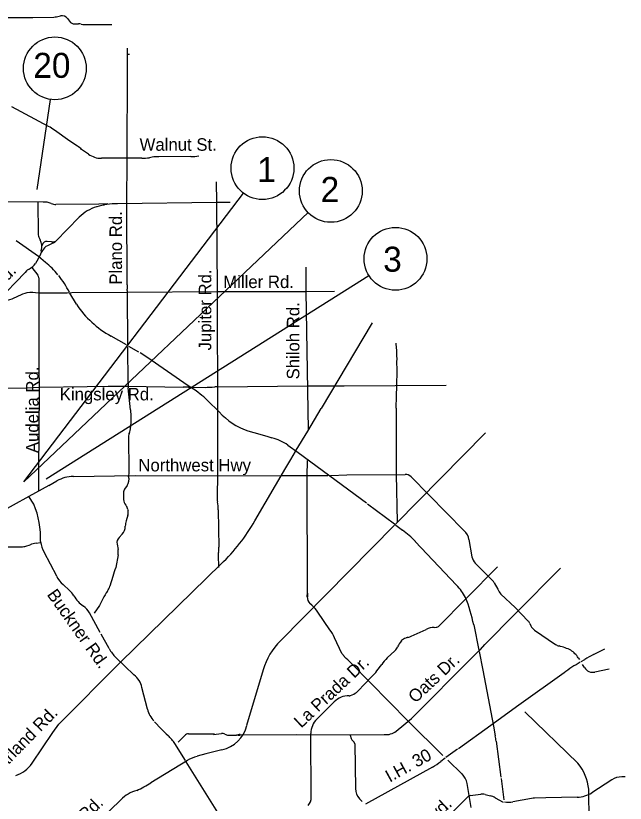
# Model space of a CAD drawing. Extents: x 105094 to 105814, y -291615 to -291123.
# Drawn here: x 105486.2 to 105545.1, y -291448 to -291371.9 of the extents above; entities that cross this region are included whole.
import ezdxf

# ---------------------------------------------------------------- set-up
doc = ezdxf.new("R2010")
doc.units = 0
doc.layers.add('G_BORDER', color=7, linetype='Continuous')
doc.layers.add('G_MAP', color=7, linetype='Continuous')

msp = doc.modelspace()

# ---------------------------------------------------------------- linework, layer by layer
at = {"layer": 'G_BORDER'}
for p, q in [((105488.251, -291388.669), (105489.525, -291379.944)), ((105486.954, -291416.932), (105508.197, -291389.007)), ((105486.954, -291416.932), (105514.44, -291390.884)), ((105489.114, -291416.641), (105520.33, -291396.975))]:
    msp.add_line(p, q, dxfattribs=at)
for centre in [(105489.964, -291376.941), (105510.034, -291386.591), (105516.643, -291388.796), (105522.898, -291395.357)]:
    msp.add_circle(centre, 3.035, dxfattribs=at)
at = {"layer": 'G_MAP'}
for p, q in [((105484.337, -291372.036), (105487.826, -291372.012)), ((105487.826, -291372.012), (105489.856, -291371.98)), ((105490.39, -291371.907), (105490.492, -291371.879)), ((105491.199, -291372.134), (105491.383, -291372.394)), ((105491.862, -291372.639), (105492.254, -291372.634)), ((105497.017, -291375.567), (105497.172, -291375.567)), ((105489.337, -291382.576), (105485.809, -291380.678)), ((105493.212, -291385.246), (105492.55, -291384.788)), ((105498.365, -291385.64), (105494.462, -291385.637)), ((105499.384, -291385.54), (105499.104, -291385.584)), ((105503.121, -291385.475), (105500.02, -291385.501)), ((105488.846, -291389.877), (105484.693, -291389.835)), ((105488.329, -291389.871), (105488.349, -291392.921)), ((105489.61, -291390.021), (105489.33, -291389.916)), ((105494.714, -291390.197), (105494.685, -291390.087)), ((105496.939, -291397.867), (105496.917, -291390.058)), ((105492.324, -291391.338), (105490.051, -291393.653)), ((105491.068, -291392.687), (105491.003, -291392.616)), ((105488.461, -291393.387), (105488.53, -291393.514)), ((105488.365, -291395.145), (105486.217, -291393.63)), ((105488.73, -291394.029), (105488.707, -291394.118)), ((105489.651, -291393.72), (105489.227, -291393.68)), ((105489.818, -291393.817), (105489.247, -291394.094)), ((105488.494, -291395.064), (105488.1, -291395.807)), ((105488.639, -291394.744), (105488.494, -291395.064)), ((105488.634, -291394.58), (105488.639, -291394.744)), ((105488.771, -291394.57), (105488.639, -291394.744)), ((105489.065, -291395.705), (105488.365, -291395.145)), ((105487.224, -291396.514), (105487.099, -291396.685)), ((105487.732, -291396.197), (105488.316, -291396.944)), ((105487.099, -291396.685), (105483.821, -291400.044)), ((105488.378, -291398.636), (105491.136, -291398.636)), ((105491.136, -291398.636), (105491.604, -291398.632)), ((105492.059, -291399.759), (105491.423, -291398.671)), ((105497.03, -291403.68), (105496.998, -291398.675)), ((105520.648, -291401.566), (105515.713, -291409.841)), ((105496.875, -291403.69), (105495.392, -291402.824)), ((105497.046, -291407.368), (105497.03, -291403.87)), ((105498.092, -291404.39), (105497.127, -291403.832)), ((105497.033, -291407.681), (105502.368, -291407.759)), ((105497.279, -291409.958), (105497.062, -291407.839)), ((105502.895, -291407.765), (105502.368, -291407.759)), ((105503.618, -291408.133), (105502.837, -291407.633)), ((105502.895, -291407.765), (105504.535, -291407.788)), ((105505.165, -291407.762), (105505.437, -291407.749)), ((105517.928, -291407.629), (105527.797, -291407.592)), ((105504.72, -291409.047), (105504.364, -291408.721)), ((105505.847, -291410.166), (105504.72, -291409.047)), ((105488.411, -291417.809), (105488.43, -291410.04)), ((105522.973, -291409.789), (105522.963, -291414.875)), ((105505.685, -291410.731), (105505.695, -291416.024)), ((105508.61, -291411.982), (105509.215, -291412.169)), ((105509.215, -291412.169), (105510.452, -291412.524)), ((105510.452, -291412.524), (105510.95, -291412.656)), ((105531.608, -291412.173), (105522.918, -291420.998)), ((105512.497, -291413.367), (105513.494, -291414.1)), ((105513.494, -291414.1), (105520.089, -291418.97)), ((105509.303, -291420.688), (105512.296, -291415.585)), ((105491.755, -291416.399), (105497.718, -291416.321)), ((105505.695, -291416.024), (105505.658, -291418.576)), ((105511.986, -291416.309), (105516.372, -291416.302)), ((105489.37, -291417.286), (105490.147, -291416.84)), ((105524.4, -291416.438), (105529.533, -291421.667)), ((105489.37, -291417.286), (105487.451, -291418.332)), ((105496.943, -291417.274), (105496.711, -291417.63)), ((105487.451, -291418.332), (105481.125, -291421.859)), ((105487.936, -291419.094), (105487.451, -291418.332)), ((105496.607, -291417.979), (105496.607, -291418.631)), ((105496.815, -291419.191), (105496.853, -291419.235)), ((105520.189, -291419.038), (105522.792, -291420.995)), ((105497.007, -291420.157), (105496.849, -291420.704)), ((105497.023, -291419.6), (105497.036, -291419.679)), ((105505.768, -291419.618), (105505.814, -291423.231)), ((105522.805, -291421.111), (105511.765, -291432.298)), ((105522.792, -291420.995), (105522.944, -291421.114)), ((105522.944, -291421.114), (105523.58, -291421.602)), ((105496.455, -291422.001), (105496.175, -291422.294)), ((105484.35, -291423.199), (105486.735, -291423.209)), ((105487.155, -291423.143), (105487.564, -291423.009)), ((105488.143, -291422.847), (105488.581, -291422.793)), ((105495.979, -291422.948), (105496.074, -291423.466)), ((105524.817, -291422.687), (105528.809, -291426.913)), ((105530.004, -291422.516), (105530.293, -291424.168)), ((105490.136, -291426.054), (105488.923, -291423.74)), ((105496.074, -291423.981), (105495.842, -291425.215)), ((105505.759, -291423.995), (105505.789, -291425.215)), ((105530.608, -291424.781), (105532.087, -291426.285)), ((105529.778, -291428.181), (105532.775, -291425.129)), ((105538.855, -291425.264), (105534.496, -291429.654)), ((105495.577, -291426.07), (105495.284, -291427.021)), ((105491.366, -291427.418), (105490.755, -291426.858)), ((105532.439, -291426.692), (105532.782, -291427.306)), ((105533.079, -291427.79), (105534.477, -291429.082)), ((105527.107, -291430.838), (105529.675, -291428.274)), ((105514.796, -291428.845), (105514.63, -291428.685)), ((105534.477, -291429.082), (105535.74, -291430.388)), ((105494.337, -291431.489), (105493.309, -291429.598)), ((105516.54, -291431.225), (105515.4, -291429.53)), ((105531.551, -291432.66), (105534.496, -291429.653)), ((105530.46, -291430.761), (105530.954, -291433.199)), ((105535.891, -291430.608), (105535.999, -291430.844)), ((105495.209, -291433.051), (105494.431, -291431.641)), ((105524.43, -291431.849), (105525.867, -291431.194)), ((105526.639, -291431), (105526.817, -291430.98)), ((105536.349, -291431.258), (105538.374, -291432.644)), ((105523.463, -291432.313), (105523.493, -291432.275)), ((105523.887, -291432.056), (105523.933, -291432.017)), ((105530.834, -291433.396), (105531.128, -291433.125)), ((105531.128, -291433.125), (105531.551, -291432.66)), ((105542.041, -291433.625), (105543.153, -291433.084)), ((105497.609, -291435.588), (105495.866, -291433.908)), ((105522.105, -291433.958), (105522.841, -291433.254)), ((105530.418, -291433.8), (105530.712, -291433.519)), ((105530.712, -291433.519), (105530.831, -291433.396)), ((105530.976, -291433.341), (105531.338, -291435.124)), ((105521.087, -291435.211), (105521.565, -291434.581)), ((105540.57, -291433.94), (105540.684, -291434.116)), ((105540.862, -291434.291), (105541.195, -291434.1)), ((105541.169, -291434.888), (105540.978, -291434.581)), ((105510.104, -291435.108), (105508.508, -291440.474)), ((105531.338, -291435.124), (105532.365, -291440.562)), ((105539.195, -291435.39), (105534.829, -291438.525)), ((105543.547, -291435.047), (105542.189, -291435.327)), ((105519.25, -291437.171), (105520.626, -291435.747)), ((105498.921, -291438.919), (105498.387, -291436.815)), ((105518.555, -291437.593), (105518.725, -291437.525)), ((105515.287, -291439.871), (105516.977, -291438.19)), ((105534.829, -291438.525), (105532.133, -291440.485)), ((105540.533, -291444.14), (105535.414, -291439.154)), ((105500.248, -291440.808), (105499.608, -291440.122)), ((105532.133, -291440.485), (105528.977, -291442.749)), ((105532.365, -291440.562), (105532.543, -291441.48)), ((105501.881, -291442.098), (105502.521, -291441.445)), ((105502.877, -291441.295), (105505.398, -291441.285)), ((105505.308, -291441.352), (105506.069, -291441.26)), ((105506.738, -291441.421), (105507.523, -291441.411)), ((105514.754, -291447.44), (105514.708, -291441.259)), ((105518.51, -291441.408), (105518.602, -291441.737)), ((105502.598, -291443.881), (105501.564, -291442.241)), ((105518.681, -291441.876), (105518.887, -291442.093)), ((105518.958, -291442.266), (105519.02, -291446.583)), ((105532.624, -291442.012), (105533.073, -291445.487)), ((105528.897, -291442.784), (105527.773, -291443.595)), ((105527.698, -291443.643), (105527.292, -291443.953)), ((105502.771, -291443.868), (105499.243, -291446.039)), ((105505.719, -291448.885), (105502.663, -291443.988)), ((105526.465, -291444.508), (105519.999, -291448.096)), ((105529.341, -291445.177), (105527.97, -291443.85)), ((105530.218, -291448.416), (105529.816, -291446.081)), ((105533.108, -291445.626), (105533.376, -291447.664)), ((105543.823, -291445.736), (105541.891, -291446.984)), ((105541.705, -291453.857), (105541.589, -291446.659)), ((105519.429, -291447.585), (105519.673, -291447.838)), ((105526.657, -291450.614), (105529.889, -291447.382)), ((105530.13, -291447.262), (105531.15, -291447.125)), ((105531.555, -291447.146), (105532.075, -291447.273)), ((105532.533, -291447.483), (105533.312, -291447.903)), ((105536.059, -291447.543), (105534.24, -291447.871)), ((105537.423, -291447.473), (105536.356, -291447.515)), ((105540.474, -291447.416), (105537.423, -291447.473))]:
    msp.add_line(p, q, dxfattribs=at)
for points in [[(105492.806, -291372.703), (105494.899, -291372.703), (105495.467, -291372.702)], [(105496.917, -291390.058), (105496.968, -291385.653), (105496.978, -291376.953), (105496.996, -291375.006)], [(105492.153, -291384.481), (105491.404, -291383.98), (105489.915, -291382.928)], [(105505.574, -291387.932), (105505.594, -291389.877)], [(105495.069, -291390.055), (105494.22, -291390.084), (105490.067, -291390.103)], [(105506.898, -291389.926), (105505.601, -291389.925), (105496.021, -291390.032)], [(105505.594, -291389.877), (105505.659, -291398.538), (105505.685, -291410.731)], [(105514.479, -291411.902), (105514.269, -291398.509), (105514.256, -291396.178)], [(105488.4, -291397.188), (105488.407, -291403.645), (105488.43, -291410.039)], [(105491.604, -291398.632), (105496.997, -291398.581), (105505.662, -291398.535), (105514.263, -291398.512), (105517.008, -291398.498)], [(105523.031, -291404.661), (105523.015, -291404.257), (105522.963, -291403.583), (105522.962, -291403.516)], [(105502.837, -291407.633), (105498.858, -291404.868), (105498.196, -291404.449)], [(105522.973, -291409.786), (105522.983, -291408.64), (105523.021, -291407.645), (105523.063, -291406.156), (105523.044, -291405.262)], [(105483.13, -291407.888), (105487.173, -291407.827), (105488.485, -291407.785), (105493.093, -291407.704), (105495.115, -291407.662), (105497.033, -291407.681)], [(105505.695, -291407.736), (105514.389, -291407.632), (105517.928, -291407.629)], [(105497.279, -291409.959), (105497.301, -291410.573), (105497.301, -291411.073), (105497.28, -291411.641)], [(105513.304, -291413.858), (105514.428, -291412.017), (105515.713, -291409.844)], [(105497.098, -291412.48), (105497.104, -291416.024), (105497.092, -291416.399)], [(105512.296, -291415.585), (105512.765, -291414.752), (105513.223, -291413.993)], [(105514.383, -291427.699), (105514.366, -291416.373), (105514.392, -291414.878)], [(105522.963, -291414.875), (105522.964, -291416.202), (105523.057, -291420.795)], [(105497.718, -291416.321), (105505.679, -291416.341), (105511.964, -291416.305)], [(105516.614, -291416.322), (105518.184, -291416.264), (105523.826, -291416.201)], [(105487.764, -291444.137), (105489.758, -291441.171), (105490.355, -291440.367), (105496.323, -291434.351), (105506.044, -291424.86)], [(105494.596, -291428.246), (105494.263, -291428.883), (105493.746, -291429.623)], [(105517.977, -291433.848), (105517.977, -291433.825), (105517.703, -291433.509), (105516.999, -291432.004)], [(105522.967, -291441.027), (105524.437, -291439.816), (105530.418, -291433.8)], [(105527.485, -291443.385), (105524.133, -291440.055), (105518.61, -291434.465)], [(105507.872, -291441.385), (105513.33, -291441.369), (105514.648, -291441.388), (105521.811, -291441.347)], [(105506.119, -291442.825), (105504.572, -291443.238), (105503.707, -291443.468)], [(105545.115, -291445.454), (105544.774, -291445.455)], [(105496.336, -291447.662), (105486.88, -291456.847), (105486.383, -291457.341)]]:
    msp.add_lwpolyline(points, dxfattribs=at)
for centre, radius, start, end in [((105489.841, -291369.884), 2.096, 270.39765, 285.19367), ((105490.664, -291372.511), 0.655, 35.19875, 105.20005), ((105491.855, -291372.061), 0.578, 215.21916, 270.70004), ((105492.261, -291373.673), 1.039, 75.57891, 90.41542), ((105492.806, -291371.555), 1.148, 255.55069, 270.00019), ((105488.574, -291384.479), 2.05, 49.16169, 68.16293), ((105491.241, -291386.073), 1.835, 44.4606, 60.18033), ((105494.463, -291383.439), 2.198, 235.30065, 269.95014), ((105498.369, -291380.854), 4.787, 269.9494, 278.83232), ((105499.84, -291387.786), 2.291, 85.4926, 101.48183), ((105503.085, -291381.737), 3.738, 270.54515, 282.3706), ((105488.991, -291391.107), 1.239, 74.11481, 96.74104), ((105490.061, -291388.822), 1.281, 249.36441, 270.27723), ((105495.074, -291394.038), 3.854, 106.12562, 135.53222), ((105496.103, -291397.423), 7.392, 90.63366, 106.49787), ((105489.296, -291392.939), 0.948, 178.9585, 208.25312), ((105487.317, -291394.17), 1.379, 342.74484, 28.41373), ((105489.183, -291394.146), 0.468, 84.60188, 165.52388), ((105489.695, -291395.019), 1.028, 115.85344, 154.059), ((105489.771, -291393.216), 0.518, 256.6181, 302.61243), ((105489.616, -291393.286), 0.569, 290.79874, 319.824), ((105486.685, -291394.814), 1.728, 296.97109, 324.95585), ((105484.252, -291401.629), 7.633, 38.11772, 50.91227), ((105488.089, -291397.574), 1.368, 116.93223, 129.194), ((105488.003, -291397.189), 0.398, 0.07759, 38.02354), ((105481.04, -291404.15), 11.734, 28.39142, 37.63494), ((105507.385, -291398.001), 10.447, 179.26481, 181.60309), ((105495.354, -291398.718), 1.644, 1.46949, 14.95875), ((105499.84, -291394.643), 9.312, 213.33038, 241.47188), ((105517.607, -291405.079), 5.44, 358.06969, 4.40048), ((105499.555, -291407.518), 2.513, 176.577, 187.34946), ((105504.538, -291400.178), 7.61, 269.97727, 274.72399), ((105505.613, -291408.687), 0.954, 85.07207, 100.65228), ((105493.547, -291421.684), 16.884, 50.15717, 53.38065), ((105510.718, -291405.764), 6.566, 222.09964, 251.27026), ((105495.57, -291411.579), 1.712, 337.11174, 357.91098), ((105497.688, -291412.48), 0.59, 156.51704, 180.08939), ((105509.108, -291418.705), 6.323, 57.59475, 73.06745), ((105491.801, -291419.721), 3.322, 90.80312, 119.8625), ((105496.162, -291416.691), 0.974, 323.25962, 17.47371), ((105523.835, -291416.993), 0.793, 44.46194, 90.65606), ((105497.246, -291417.979), 0.639, 146.91283, 180.00003), ((105497.465, -291418.631), 0.858, 179.99785, 220.73534), ((105506.725, -291418.582), 1.067, 179.6825, 195.06943), ((105480.346, -291422.271), 8.228, 356.95636, 22.71465), ((105496.292, -291419.718), 0.74, 9.20961, 40.75888), ((105501.03, -291419.688), 4.738, 0.84507, 10.06711), ((105495.967, -291419.855), 1.083, 343.80523, 9.31763), ((105498.655, -291421.227), 1.881, 163.84518, 179.44566), ((105493.37, -291411.603), 18.341, 313.71172, 330.30768), ((105495.627, -291421.207), 1.148, 316.21885, 359.90301), ((105519.31, -291427.718), 7.46, 42.40817, 55.0725), ((105528.764, -291422.649), 1.248, 6.12479, 51.94908), ((105496.718, -291422.813), 0.751, 136.24156, 190.39225), ((105486.74, -291421.879), 1.33, 269.77251, 288.17114), ((105488.656, -291425.802), 2.999, 99.86042, 111.34683), ((105492.727, -291421.83), 4.256, 191.91108, 206.66429), ((105501.292, -291423.291), 4.522, 354.26759, 0.75953), ((105494.696, -291423.721), 1.402, 349.32009, 10.48952), ((105506.617, -291423.977), 0.858, 164.10347, 181.21373), ((105531.434, -291423.969), 1.158, 189.90824, 224.51192), ((105503.9, -291428.177), 8.585, 159.81449, 165.79566), ((105492.754, -291424.679), 2.957, 207.69819, 227.46392), ((105531.441, -291427.2), 1.12, 26.96282, 54.76235), ((105493.706, -291426.538), 1.651, 325.08193, 342.99069), ((105524.665, -291430.828), 5.701, 28.44562, 43.37026), ((105489.819, -291429.106), 2.289, 30.44854, 47.47928), ((105500.817, -291431.503), 7.021, 145.07819, 152.371), ((105513.605, -291427.678), 0.778, 345.02891, 358.46815), ((105515.161, -291427.72), 0.778, 178.46807, 191.90731), ((105536.61, -291425.291), 4.327, 207.75798, 215.28898), ((105494.51, -291426.34), 3.156, 210.5845, 235.33535), ((105515.109, -291428.08), 0.778, 165.02871, 178.46796), ((105515.212, -291428.081), 0.839, 178.61951, 226.07268), ((105513.638, -291428.041), 0.778, 358.46815, 11.90739), ((105516.674, -291433.39), 14.034, 10.79874, 22.08957), ((105491.624, -291430.514), 1.918, 28.51258, 55.34422), ((105512.758, -291431.251), 3.153, 33.09172, 49.73924), ((105526.874, -291430.729), 0.258, 257.2058, 334.89597), ((105535.167, -291430.942), 0.797, 24.75363, 43.99801), ((105536.926, -291430.416), 1.021, 204.77618, 235.6006), ((105514.602, -291432.891), 2.555, 20.32723, 40.68868), ((105526.607, -291432.509), 1.509, 88.80403, 119.37389), ((105516.555, -291437.025), 6.729, 135.3756, 163.44959), ((105525.709, -291434.107), 2.874, 141.37346, 154.82071), ((105523.95, -291432.632), 0.579, 96.22067, 142.04225), ((105524.164, -291432.477), 0.515, 96.28781, 116.66667), ((105524.025, -291431.232), 0.738, 276.37152, 303.25306), ((105498.377, -291431.303), 3.618, 208.89973, 226.05435), ((105521.979, -291432.351), 1.248, 313.66684, 334.71895), ((105538.96, -291431.79), 1.036, 235.54143, 256.58261), ((105537.515, -291437.858), 5.202, 63.19227, 76.60712), ((105506.904, -291445.845), 16.326, 44.18911, 47.29127), ((105538.452, -291435.305), 2.52, 32.80053, 56.01509), ((105546.271, -291442.156), 9.522, 116.37593, 122.21653), ((105524.304, -291436.406), 3.291, 131.9352, 146.32347), ((105553.168, -291454.858), 23.964, 121.20477, 125.66668), ((105518.128, -291433.128), 3.619, 313.64483, 324.86542), ((105541.993, -291434.376), 0.97, 211.85203, 281.6258), ((105496.24, -291437.316), 2.205, 13.14567, 51.62308), ((105518.367, -291439.589), 1.972, 88.69163, 134.81345), ((105518.426, -291437.277), 0.342, 267.50914, 292.10733), ((105518.157, -291436.116), 1.519, 291.95186, 315.99579), ((105501.431, -291438.282), 2.59, 194.24083, 223.08986), ((105516.67, -291441.262), 1.962, 134.8232, 179.89797), ((105505.528, -291439.835), 3.048, 281.16497, 347.89455), ((105508.297, -291433.299), 11.008, 223.01136, 227.8573), ((105498.353, -291444.265), 3.795, 32.22504, 47.63082), ((105502.879, -291441.796), 0.501, 90.21921, 135.60849), ((105506.134, -291441.8), 0.543, 59.22349, 96.87847), ((105506.731, -291440.798), 0.623, 239.22904, 270.65371), ((105507.47, -291440.698), 0.715, 274.27321, 288.29996), ((105507.577, -291442.124), 0.715, 80.24654, 94.27329), ((105507.919, -291442.055), 0.715, 94.27328, 108.30003), ((105507.819, -291440.714), 0.715, 260.24646, 274.27321), ((105522.024, -291439.867), 1.495, 261.80149, 309.10963), ((105529.651, -291442.19), 2.978, 3.42655, 13.80865), ((105518.921, -291441.648), 0.331, 195.54549, 223.46667), ((105518.699, -291442.271), 0.258, 0.98226, 43.51745), ((105504.697, -291447.188), 3.849, 104.9058, 120.11274), ((105485.315, -291442.491), 2.951, 287.03231, 326.08708), ((105524.064, -291440.042), 5.071, 298.25743, 309.52995), ((105537.061, -291447.077), 4.547, 5.26931, 40.22336), ((105528.204, -291446.351), 1.635, 9.53388, 45.93204), ((105493.322, -291436.507), 11.222, 294.00049, 301.84641), ((105544.778, -291447.216), 1.761, 90.14363, 122.84297), ((105498.937, -291450.342), 3.735, 106.33736, 134.14216), ((105520.48, -291446.572), 1.459, 180.41823, 223.96618), ((105513.677, -291447.465), 1.078, 316.09537, 1.2822), ((105530.187, -291447.68), 0.421, 97.68019, 134.97644), ((105531.296, -291448.206), 1.091, 76.25248, 97.70733), ((105531.575, -291448.971), 1.77, 57.21534, 73.59463), ((105536.384, -291449.35), 1.835, 90.86911, 100.1992), ((105540.423, -291444.71), 2.706, 271.08575, 302.84675), ((105533.845, -291445.669), 2.238, 259.77082, 280.18014)]:
    msp.add_arc(centre, radius, start, end, dxfattribs=at)
msp.add_spline([(105463.027, -291396.395), (105466.797, -291396.395), (105468.945, -291397.601), (105472.732, -291398.475), (105476.336, -291397.455), (105480.413, -291397.455), (105482.925, -291398.475), (105484.746, -291399.423), (105486.457, -291398.949), (105487.284, -291398.616), (105488.378, -291398.636)], degree=3, dxfattribs=at)

# ---------------------------------------------------------------- texts
at = {"layer": 'G_BORDER'}
for s, p in [('20', (105487.876, -291377.86)), ('1', (105509.531, -291387.944)), ('2', (105515.661, -291389.857)), ('3', (105521.708, -291396.606))]:
    msp.add_text(s, height=2.416, dxfattribs=at).set_placement(p)
at = {"layer": 'G_MAP'}
for s, height, p in [('Walnut St.', 1.2111, (105498.153, -291384.912)), ('Miller Rd.', 1.2111, (105506.242, -291398.187)), ('Kingsley Rd.', 1.21107, (105490.434, -291409.051)), ('Northwest Hwy', 1.21107, (105498.035, -291415.914))]:
    msp.add_text(s, height=height, dxfattribs=at).set_placement(p)
for s, height, rotation, p in [('Plano Rd.', 1.2111, 90, (105496.455, -291397.865)), ('Skillman Rd.', 1.21107, 45.49919, (105479.96, -291403.08)), ('Jupiter Rd.', 1.21107, 90, (105505.089, -291404.219)), ('Shiloh Rd.', 1.2111, 90, (105513.603, -291407.025)), ('Audelia Rd.', 1.21107, 90, (105488.384, -291414.149)), ('Buckner Rd.', 1.21107, 305.4513, (105489.146, -291427.831)), ('Oats Dr.', 1.2111, 43.22017, (105524.819, -291438.389)), ('La Prada Dr.', 1.21107, 43.22017, (105513.776, -291440.794)), ('Garland Rd.', 1.21107, 45.55826, (105484.224, -291445.583)), ('I.H. 30', 1.2111, 28.95746, (105522.339, -291446.017)), ('Ferguson Rd.', 1.21107, 43.6217, (105487.646, -291454.843)), ('Town East Blvd.', 1.21107, 43.22017, (105519.929, -291456.204))]:
    msp.add_text(s, height=height, rotation=rotation, dxfattribs=at).set_placement(p)

doc.saveas('drawing.dxf')
